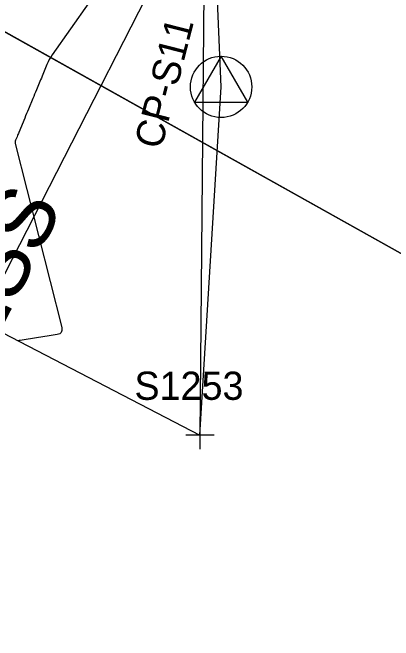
# Model space of a CAD drawing. Extents: x 816928 to 825690, y 436959 to 448212.
# Drawn here: x 818913.6 to 818967.6, y 444413.7 to 444502.7 of the extents above; entities that cross this region are included whole.
import ezdxf

# ---------------------------------------------------------------- set-up
doc = ezdxf.new("R2010")
doc.units = 0
for name, color, linetype in [('DESIGN - SCRATCH - User 1', 7, 'Continuous'), ('SURVEY - CONTOURS - Intermediate with optional Text', 7, 'Continuous'), ('SURVEY - CONTROL with Text', 7, 'Continuous'), ('SURVEY - PROPERTY - Owners', 7, 'Continuous'), ('SURVEY - PROPERTY - Parcels', 7, 'Continuous'), ('SURVEY - PROPERTY - Property Lines', 7, 'Continuous'), ('SURVEY - VEGETATION - Features - Points - Locators', 7, 'Continuous'), ('SURVEY - VEGETATION - Features - Points - Numbers', 7, 'Continuous'), ('SURVEY - VEGETATION - Features with Text', 7, 'Continuous')]:
    doc.layers.add(name, color=color, linetype=linetype)

msp = doc.modelspace()

# ---------------------------------------------------------------- linework, layer by layer
at = {"layer": 'DESIGN - SCRATCH - User 1'}
msp.add_lwpolyline([(818640.147, 444520.892), (818676.038, 444463.993), (818725.201, 444432.827), (818735.804, 444428.835), (818765.207, 444431.593), (818770.156, 444432.208), (818775.104, 444432.822), (818780.053, 444433.437), (818785.002, 444434.051), (818789.95, 444434.665), (818789.97, 444434.668), (818836.244, 444442.278), (818836.31, 444442.343), (818839.883, 444445.84), (818843.456, 444449.337), (818847.029, 444452.835), (818850.602, 444456.332), (818884.078, 444471.852), (818940.13, 444442.798), (818943.136, 444492.177), (818941.02, 444542.4)], dxfattribs=at)
at = {"layer": 'SURVEY - CONTOURS - Intermediate with optional Text'}
msp.add_lwpolyline([(818924.383, 444504.072), (818919.175, 444496.702), (818918.961, 444496.381), (818918.766, 444496.049), (818918.589, 444495.707), (818918.432, 444495.355), (818917.947, 444494.186), (818917.843, 444493.936), (818917.74, 444493.686), (818917.636, 444493.436), (818917.532, 444493.185), (818916.935, 444491.746), (818916.807, 444491.438), (818916.68, 444491.129), (818916.552, 444490.821), (818916.424, 444490.512), (818915.805, 444489.02), (818915.673, 444488.7), (818915.54, 444488.381), (818915.407, 444488.061), (818915.275, 444487.741), (818914.438, 444485.724), (818914.375, 444485.57), (818914.311, 444485.417), (818914.248, 444485.264), (818914.184, 444485.111), (818913.977, 444484.61), (818913.941, 444484.502), (818913.924, 444484.393), (818913.925, 444484.282), (818913.944, 444484.17), (818920.521, 444458.036), (818920.561, 444457.655), (818920.465, 444457.364), (818920.235, 444457.161), (818919.87, 444457.048), (818918.456, 444456.823), (818918.153, 444456.775), (818917.85, 444456.727), (818917.547, 444456.678), (818917.244, 444456.63), (818914.635, 444456.215), (818914.601, 444456.209), (818914.566, 444456.204), (818914.532, 444456.198), (818914.498, 444456.193), (818914.337, 444456.167)], dxfattribs=at)
at = {"layer": 'SURVEY - CONTROL with Text'}
for p, q in [((818943.136, 444496.527), (818939.369, 444490.002)), ((818946.904, 444490.002), (818943.136, 444496.527)), ((818943.136, 444492.177), (818943.136, 444492.177)), ((818939.369, 444490.002), (818946.904, 444490.002))]:
    msp.add_line(p, q, dxfattribs=at)
msp.add_circle((818943.136, 444492.177), 4.35, dxfattribs=at)
at = {"layer": 'SURVEY - PROPERTY - Owners'}
msp.add_line((818847.641, 444339.227), (818935.755, 444511.205), dxfattribs=at)
at = {"layer": 'SURVEY - PROPERTY - Parcels'}
msp.add_line((819226.308, 444324.647), (818742.759, 444594.722), dxfattribs=at)
at = {"layer": 'SURVEY - PROPERTY - Property Lines'}
msp.add_line((818742.759, 444594.722), (819226.308, 444324.647), dxfattribs=at)
at = {"layer": 'SURVEY - VEGETATION - Features - Points - Locators'}
for p, q in [((818940.13, 444444.798), (818940.13, 444440.798)), ((818942.13, 444442.798), (818938.13, 444442.798))]:
    msp.add_line(p, q, dxfattribs=at)
at = {"layer": 'SURVEY - VEGETATION - Features with Text'}
msp.add_lwpolyline([(818956.676, 444741.89), (818960.538, 444710.463), (818950.738, 444625.43), (818941.02, 444542.4), (818940.13, 444442.798)], dxfattribs=at)

# ---------------------------------------------------------------- texts
at = {"layer": 'SURVEY - CONTROL with Text'}
msp.add_text('CP-S11', height=4, rotation=75.68949, dxfattribs=at).set_placement((818934.651, 444483.188))
at = {"layer": 'SURVEY - PROPERTY - Owners'}
for s, rotation, p in [('LUTHER F. BRYANT', 54.68153, (818868.303, 444491.264)), ('EYUX REBA BRYANT', 54.68153, (818880.338, 444482.736)), ('ETUX SUSAN L. FORBESS', 63.12559, (818854.303, 444344.036))]:
    msp.add_text(s, height=8.75, rotation=rotation, dxfattribs=at).set_placement(p)
at = {"layer": 'SURVEY - VEGETATION - Features - Points - Numbers'}
msp.add_text('S1253', height=4, dxfattribs=at).set_placement((818930.842, 444447.798))

doc.saveas('drawing.dxf')
